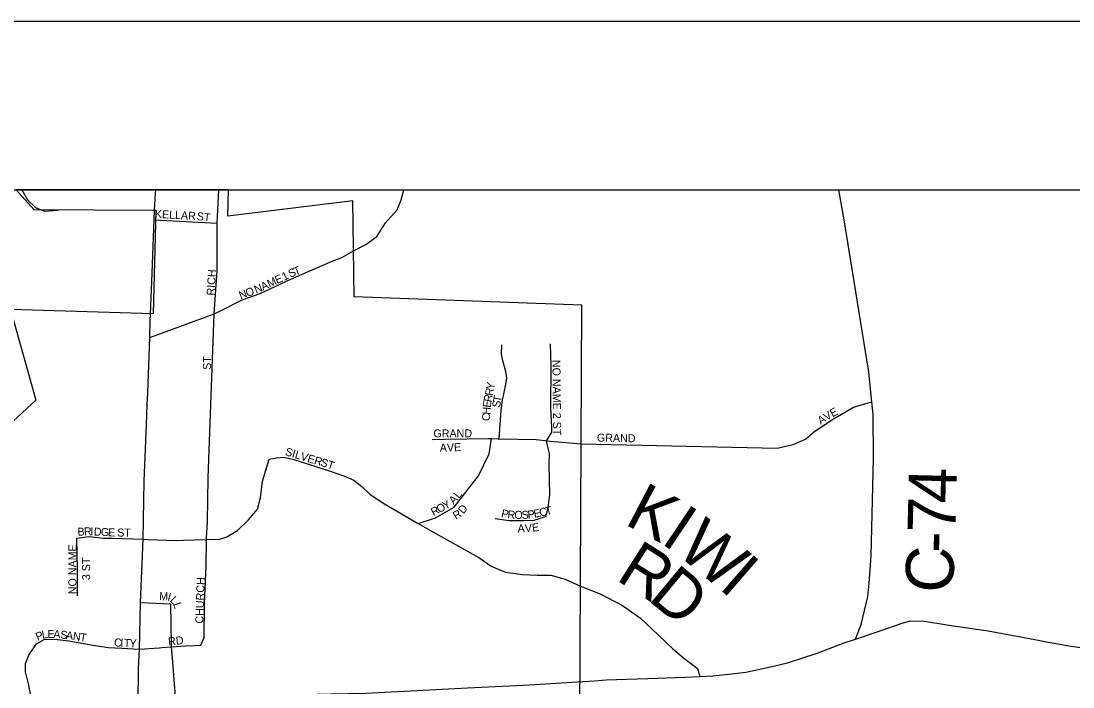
# Model space of a CAD drawing. Extents: x -22 to 431, y -18 to 160.
# Drawn here: x 328.287 to 329.532, y 159.331 to 160.12 of the extents above; entities that cross this region are included whole.
import ezdxf

# ---------------------------------------------------------------- set-up
doc = ezdxf.new("R2010")
doc.units = 0
for name, color, linetype in [('GM_X_Adjacent_County_Text', 7, 'Continuous'), ('GM_X_City_Street', 7, 'Continuous'), ('GM_X_City_Street_Text', 7, 'Continuous'), ('GM_X_Corporation_Text', 7, 'Continuous'), ('GM_X_County_ROW', 7, 'Continuous'), ('GM_X_County_Subdivision', 7, 'Continuous'), ('GM_X_County_Subdivision_Text', 7, 'Continuous'), ('GM_X_Minor_River_Text', 7, 'Continuous'), ('GM_X_Section', 7, 'Continuous'), ('GM_X_Section_Text', 7, 'Continuous'), ('GM_X_Township_ROW', 7, 'Continuous')]:
    doc.layers.add(name, color=color, linetype=linetype)

msp = doc.modelspace()

# ---------------------------------------------------------------- linework, layer by layer
at = {"layer": 'GM_X_Adjacent_County_Text'}
for points in [[(328.2877, 159.9199), (328.2944, 159.9081), (328.3041, 159.8992), (328.3144, 159.8949), (328.3309, 159.8961)], [(329.2745, 159.3879), (329.281, 159.4053), (329.289, 159.4384), (329.2904, 159.4544), (329.2931, 159.4866), (329.2959, 159.602), (329.2955, 159.654), (329.2939, 159.669), (329.2901, 159.704), (329.2614, 159.8821), (329.2546, 159.9199)]]:
    msp.add_lwpolyline(points, dxfattribs=at)
at = {"layer": 'GM_X_County_ROW'}
msp.add_line((328.446, 159.9155), (328.4462, 159.9199), dxfattribs=at)
for points in [[(328.4397, 159.7659), (328.4399, 159.773), (328.4415, 159.8112), (328.4444, 159.8844), (328.4447, 159.8958), (328.446, 159.9155)], [(328.4362, 159.666), (328.4368, 159.6796), (328.4392, 159.7453), (328.4397, 159.7659)], [(328.4312, 159.5061), (328.4313, 159.5063), (328.4327, 159.5749), (328.4352, 159.6422), (328.4362, 159.666)], [(328.4269, 159.3762), (328.4284, 159.4308), (328.4312, 159.5061)], [(329.1804, 159.3568), (329.1807, 159.3569), (329.194, 159.3599), (329.2291, 159.3715), (329.2611, 159.3834), (329.2745, 159.3879), (329.3, 159.3966), (329.3309, 159.4073), (329.34, 159.4098), (329.3555, 159.4093), (329.3902, 159.4038), (329.4313, 159.3976), (329.4865, 159.3875), (329.5005, 159.3849), (329.5005, 159.3849)], [(328.4254, 159.3149), (328.4259, 159.3528), (328.4269, 159.3762)], [(329.5005, 159.3849), (329.5295, 159.3795), (329.5611, 159.3754)], [(328.9651, 159.3387), (328.9651, 159.3387), (328.9795, 159.3396), (329.0288, 159.3415), (329.0724, 159.343), (329.0901, 159.3437), (329.1054, 159.3443), (329.1281, 159.347), (329.1448, 159.3488), (329.1648, 159.3533), (329.1804, 159.3568)], [(328.4254, 159.3149), (328.4254, 159.3149), (328.4701, 159.3147), (328.5359, 159.3191), (328.5747, 159.3213), (328.6534, 159.3231), (328.6948, 159.3239), (328.7554, 159.3271), (328.8153, 159.3304), (328.8813, 159.3334), (328.9389, 159.337), (328.9651, 159.3387)]]:
    msp.add_lwpolyline(points, dxfattribs=at)
at = {"layer": 'GM_X_County_Subdivision_Text'}
msp.add_lwpolyline([(328.9477, 159.2129), (328.9506, 159.7835), (328.6811, 159.7935), (328.6796, 159.9071), (328.5317, 159.889), (328.5322, 159.9199), (328.2809, 159.9199), (328.3018, 159.8966), (328.4462, 159.8958), (328.4431, 159.773), (328.2744, 159.7785), (328.3043, 159.6711), (328.218, 159.5913)], dxfattribs=at)
at = {"layer": 'GM_X_Minor_River_Text'}
for points in [[(328.6804, 159.8476), (328.6949, 159.8551), (328.7078, 159.8648), (328.7183, 159.8809), (328.7319, 159.8965), (328.7366, 159.9082), (328.7397, 159.9199)], [(328.9489, 159.4505), (328.9722, 159.4416), (328.9988, 159.4278), (329.0201, 159.4128), (329.041, 159.3932), (329.0582, 159.3766), (329.073, 159.3642), (329.0837, 159.356), (329.0875, 159.353), (329.0901, 159.3437)], [(328.3004, 159.3103), (328.2959, 159.3336), (328.2921, 159.3493), (328.2921, 159.3589), (328.2961, 159.3689), (328.3051, 159.3824)]]:
    msp.add_lwpolyline(points, dxfattribs=at)
at = {"layer": 'GM_X_Section'}
msp.add_line((319.5549, 159.9199), (331.7949, 159.9199), dxfattribs=at)
msp.add_lwpolyline([(319.3549, 160.1199), (331.9949, 160.1199), (331.9949, 147.4799), (319.3549, 147.4799)], close=True, dxfattribs=at)
at = {"layer": 'GM_X_Section_Text'}
for points in [[(328.5153, 159.7731), (328.5188, 159.8245), (328.5188, 159.8804), (328.521, 159.9199)], [(328.4444, 159.8844), (328.5188, 159.8804)], [(328.5245, 159.7777), (328.5487, 159.7896), (328.5698, 159.7973), (328.6069, 159.8145), (328.655, 159.8356), (328.6663, 159.84), (328.6804, 159.8476)], [(328.4392, 159.7453), (328.5153, 159.7731), (328.5245, 159.7777)], [(328.5064, 159.5077), (328.5074, 159.5269), (328.5085, 159.5789), (328.5153, 159.7731)], [(328.8526, 159.6252), (328.8538, 159.6425), (328.8551, 159.6588), (328.8567, 159.6709), (328.8602, 159.6876), (328.8618, 159.6975), (328.8604, 159.7047), (328.857, 159.7177), (328.8556, 159.726), (328.8557, 159.7363)], [(328.9081, 159.5331), (328.9108, 159.5437), (328.9125, 159.5589), (328.912, 159.5942), (328.9121, 159.6079), (328.9095, 159.6189), (328.9088, 159.6229), (328.9149, 159.6329), (328.9149, 159.6386), (328.914, 159.6618), (328.9143, 159.7115), (328.9134, 159.7378)], [(328.7568, 159.5249), (328.7775, 159.5317), (328.7996, 159.5441), (328.8283, 159.5815), (328.8407, 159.6072), (328.8435, 159.6254)], [(328.7736, 159.6244), (328.7892, 159.6247), (328.84, 159.6255), (328.8435, 159.6254), (328.8517, 159.6252), (328.852, 159.6252)], [(328.852, 159.6252), (328.8526, 159.6252), (328.8966, 159.6243), (328.9072, 159.6231), (328.9088, 159.6229), (328.9497, 159.6193)], [(328.4791, 159.505), (328.5063, 159.5058), (328.5223, 159.5065), (328.5302, 159.5092), (328.5429, 159.5166), (328.5562, 159.5291), (328.5665, 159.542), (328.5701, 159.5552), (328.5726, 159.5751), (328.5806, 159.6012), (328.5889, 159.6026), (328.5977, 159.6033)], [(328.5977, 159.6033), (328.6098, 159.6006), (328.6469, 159.5889), (328.6689, 159.5815), (328.6806, 159.5761), (328.69, 159.5685), (328.7002, 159.5593), (328.7168, 159.5481), (328.7399, 159.5347), (328.7568, 159.5249), (328.7705, 159.517), (328.8288, 159.4846), (328.8431, 159.4743), (328.8601, 159.4673), (328.8802, 159.4645), (328.8977, 159.4636), (328.9137, 159.4635), (328.9307, 159.4588), (328.9489, 159.4505)], [(328.8481, 159.5308), (328.8644, 159.5284), (328.8815, 159.5283), (328.894, 159.529), (328.9081, 159.5331)], [(328.3528, 159.5075), (328.3669, 159.5093), (328.3846, 159.5077), (328.3948, 159.5074)], [(328.3535, 159.4393), (328.3537, 159.4701), (328.3528, 159.5075)], [(328.3948, 159.5074), (328.4313, 159.5063), (328.437, 159.5061)], [(328.437, 159.5061), (328.4707, 159.5047), (328.4791, 159.505)], [(328.4996, 159.3807), (328.5035, 159.3897), (328.5038, 159.4296), (328.5058, 159.4746), (328.5063, 159.5058), (328.5064, 159.5077)], [(328.465, 159.3812), (328.4642, 159.4292), (328.4284, 159.4308)], [(328.3051, 159.3824), (328.3144, 159.3874), (328.3269, 159.388), (328.3436, 159.386), (328.3724, 159.3809), (328.3902, 159.3781), (328.4062, 159.3772), (328.4269, 159.3762), (328.4505, 159.3777)], [(328.4505, 159.3777), (328.4535, 159.3779), (328.4651, 159.3788), (328.4809, 159.3799), (328.4924, 159.3802), (328.4996, 159.3807)], [(328.4872, 159.1684), (328.4836, 159.1961), (328.4744, 159.2569), (328.4701, 159.3147), (328.4666, 159.3608), (328.4651, 159.3788), (328.465, 159.3812)]]:
    msp.add_lwpolyline(points, dxfattribs=at)
at = {"layer": 'GM_X_Township_ROW'}
msp.add_lwpolyline([(328.9497, 159.6193), (329.1817, 159.614), (329.2005, 159.6183), (329.2152, 159.6249), (329.2261, 159.6341), (329.2483, 159.649), (329.272, 159.6625), (329.2939, 159.669)], dxfattribs=at)

# ---------------------------------------------------------------- texts
at = {"layer": 'GM_X_City_Street'}
for s, rotation, p in [('4', 88.5629, (329.3935, 159.5483)), ('7', 88.4405, (329.3926, 159.5131)), ('-', 88.0501, (329.3918, 159.4894)), ('C', 87.0089, (329.3893, 159.4417))]:
    msp.add_text(s, height=0.0568, rotation=rotation, dxfattribs=at).set_placement(p)
at = {"layer": 'GM_X_City_Street_Text'}
for s, rotation, p in [('K', 332.3939, (328.9997, 159.5246)), ('I', 326.1541, (329.0426, 159.5023)), ('W', 320.661, (329.0608, 159.4902)), ('R', 327.6599, (328.9895, 159.4589)), ('D', 320.2607, (329.0274, 159.4351)), ('I', 319.121, (329.1114, 159.4487))]:
    msp.add_text(s, height=0.0568, rotation=rotation, dxfattribs=at).set_placement(p)
at = {"layer": 'GM_X_Corporation_Text'}
for s, rotation, p in [('KELLAR', 356.8776, (328.445, 159.8869)), ('ST', 352.8716, (328.4943, 159.8844)), ('RICH', 86.5336, (328.5158, 159.7946)), ('S', 23.4839, (328.6056, 159.8158)), ('T', 22.8721, (328.6117, 159.8184)), ('A', 25.0719, (328.5732, 159.8004)), ('M', 25.3938, (328.5808, 159.804)), ('E', 25.4057, (328.5899, 159.8083)), ('1', 25.3922, (328.5981, 159.8122)), ('N', 20.6302, (328.5468, 159.7902)), ('O', 20.6228, (328.5546, 159.7931)), ('N', 22.5164, (328.5651, 159.7971)), ('ST', 90, (328.5116, 159.7069)), ('NO NAME 2 ST', 270.5969, (328.9157, 159.7186)), ('Y', 78.9074, (328.8463, 159.6829)), ('R', 78.8806, (328.8434, 159.6681)), ('R', 78.8695, (328.8449, 159.6755)), ('T', 80.0104, (328.8547, 159.6681)), ('H', 85.9223, (328.8421, 159.6535)), ('E', 83.3732, (328.8427, 159.6617)), ('S', 79.9762, (328.8535, 159.6615)), ('C', 85.8927, (328.8416, 159.646)), ('GRAND', 0, (328.7749, 159.6269)), ('SILVER', 343.0731, (328.5987, 159.606)), ('A', 0.8634, (328.7825, 159.6099)), ('V', 2.2189, (328.791, 159.6101)), ('E', 2.5785, (328.7994, 159.6104)), ('ST', 341.5607, (328.6404, 159.5935)), ('Y', 28.5982, (328.7889, 159.541)), ('A', 46.4257, (328.7988, 159.547)), ('L', 52.0005, (328.8052, 159.5538)), ('R', 28.6075, (328.775, 159.5335)), ('O', 28.5982, (328.7816, 159.537)), ('R', 31.699, (328.8015, 159.5292)), ('D', 51.7705, (328.8105, 159.5355)), ('P', 347.9453, (328.8546, 159.5327)), ('R', 354.4523, (328.8622, 159.5311)), ('O', 359.7787, (328.8707, 159.5304)), ('S', 2.3153, (328.8795, 159.5303)), ('P', 5.4199, (328.8867, 159.5306)), ('E', 12.1437, (328.8945, 159.5315)), ('C', 13.4172, (328.9013, 159.5329)), ('T', 13.5669, (328.9086, 159.5347)), ('V', 3.8395, (328.8833, 159.5145)), ('E', 7.3107, (328.8922, 159.5151)), ('B', 3.037, (328.3539, 159.5103)), ('R', 1.4812, (328.3614, 159.5107)), ('I', 357.836, (328.3687, 159.5109)), ('D', 356.9717, (328.3728, 159.5107)), ('G', 356.7304, (328.3811, 159.5103)), ('E', 357.3969, (328.3896, 159.5098)), ('ST', 0, (328.4007, 159.5094)), ('A', 2.4378, (328.8747, 159.5141)), ('NO NAME', 90, (328.3524, 159.4411)), ('3 ST', 90, (328.3686, 159.4578)), ('CHURCH', 88.0262, (328.5024, 159.4062)), ('M', 357.27, (328.4502, 159.4342)), ('I', 343.5185, (328.4595, 159.4339)), ('L', 316.0157, (328.4625, 159.4333)), ('L', 288.5128, (328.4667, 159.4296)), ('P', 22.9456, (328.3065, 159.3859)), ('L', 8.8334, (328.3121, 159.3883)), ('E', 0.4508, (328.3183, 159.3893)), ('A', 356.0405, (328.3248, 159.3894)), ('S', 354.197, (328.333, 159.3888)), ('A', 352.8777, (328.3396, 159.3881)), ('N', 351.788, (328.3478, 159.3871)), ('T', 351.5665, (328.356, 159.3859)), ('C', 357.1449, (328.3967, 159.3794)), ('I', 357.163, (328.4042, 159.3791)), ('T', 357.1581, (328.4083, 159.3789)), ('Y', 357.1463, (328.415, 159.3785)), ('RD', 6.0054, (328.4614, 159.3803))]:
    msp.add_text(s, height=0.00947, rotation=rotation, dxfattribs=at).set_placement(p)
at = {"layer": 'GM_X_County_Subdivision'}
for s, rotation, p in [('E', 27.9093, (329.2471, 159.6505)), ('A', 32.4293, (329.2332, 159.6417)), ('V', 32.4372, (329.2402, 159.6461)), ('GRAND', 358.8315, (328.9683, 159.6219))]:
    msp.add_text(s, height=0.00947, rotation=rotation, dxfattribs=at).set_placement(p)

doc.saveas('drawing.dxf')
